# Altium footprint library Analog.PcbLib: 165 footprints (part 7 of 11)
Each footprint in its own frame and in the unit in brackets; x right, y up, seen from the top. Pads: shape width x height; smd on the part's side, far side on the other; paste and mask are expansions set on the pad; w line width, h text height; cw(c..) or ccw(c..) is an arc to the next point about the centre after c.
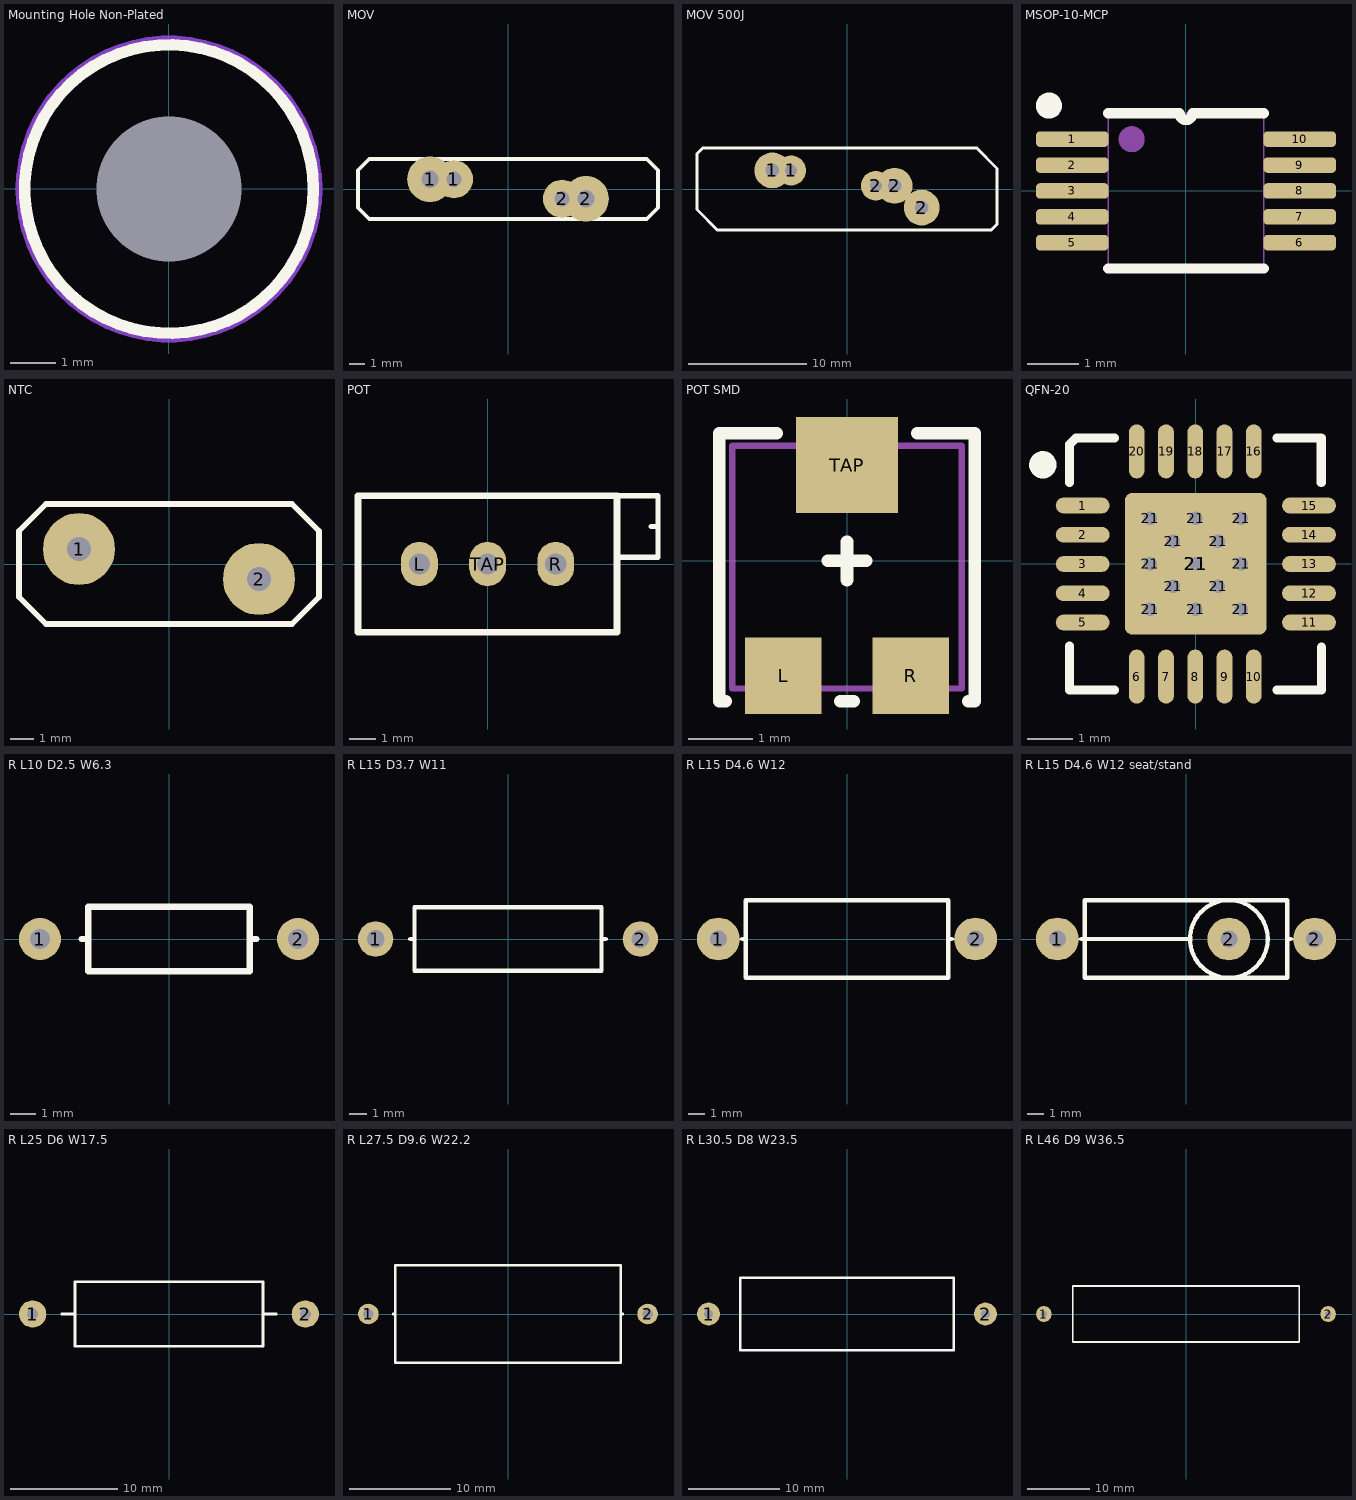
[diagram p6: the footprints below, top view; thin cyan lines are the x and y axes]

## Mounting Hole Non-Plated [mil]
pads (1):
  round 0 hole 126 unplated mask+120: 0(0,0)
Top Layer keep-out:
  circle w6: c0,0 r130
Bottom Layer keep-out:
  circle w6: c0,0 r130
Top Overlay:
  circle w10: c0,0 r125
Bottom Overlay:
  circle w10: c0,0 r125

## MOV [mil]
pads (4):
  round 120 hole 45: 1(-204.72,25.59) 2(204.72,-25.59)
  round 100 hole 40: 1(-141.73,25.59) 2(141.73,-25.59)
Top Overlay:
  lines w10: -393.7,-49.21 -393.7,49.21 -364.17,78.74 364.17,78.74 393.7,49.21 393.7,-49.21 364.17,-78.74 -364.17,-78.74 -393.7,-49.21

## MOV 500J [mil]
pads (5):
  round 120 hole 45: 1(-250,62.01) 2(159.45,10.83) 2(250,-62.01)
  round 100 hole 40: 1(-187.01,62.01) 2(96.46,10.83)
Top Overlay:
  lines w10: -501.97,-68.9 -501.97,118.11 -482.28,137.8 433.07,137.8 501.97,68.9 501.97,-118.11 482.28,-137.8 -433.07,-137.8 -501.97,-68.9

## MSOP-10-MCP [mm] "=VSSOP-10-TI"
pads (10):
  rrect50% 1.4x0.3 smd mask+0.05: 1(-2.2,1) 2(-2.2,0.5) 3(-2.2,0) 4(-2.2,-0.5) 5(-2.2,-1) 6(2.2,-1) 7(2.2,-0.5) 8(2.2,0) 9(2.2,0.5) 10(2.2,1)
Top Overlay:
  circle w0.254: c-2.65,1.65 r0.125
  lines w0.2: -1.5,-1.5 1.5,-1.5 ; -1.5,1.5 -0.125,1.5 ccw(c0,1.5) 0.125,1.5 1.5,1.5
Mechanical 13:
  circle w0.254: c-1.05,1 r0.125
  lines w0.025: -1.5,-1.5 1.5,-1.5 1.5,1.5 -1.5,1.5 -1.5,-1.5
  text ".Designator" at -0.325,1.3 h0.76

## NTC [mil]
pads (2):
  round 120 hole 40: 1(-150,25) 2(150,-25)
Top Overlay:
  lines w10: -250,-55 -205,-100 205,-100 250,-55 250,55 205,100 -205,100 -250,55 -250,-55

## POT [mil]
height 400
pads (3):
  oval 54x65 hole 31: L(-100,0) R(100,0) TAP(0,0)
Top Overlay:
  lines w8: 190,10 250,10 250,100 190,100 ; 240,55 250,55
  lines w10: -190,-100 190,-100 190,100 -190,100 -190,-100

## POT SMD [mm]
pads (3):
  rect 1.2x1.2 smd: L(-1,-1.8) R(1,-1.8)
  rect 1.6x1.5 smd: TAP(0,1.5)
Top Overlay:
  lines w0.2: -1.9,-2.2 -2,-2.2 -2,2 -1.1,2 ; -0.3,0 0.3,0 ; -0.1,-2.2 0.1,-2.2 ; 0,-0.3 0,0.3 ; 1.1,2 2,2 2,-2.2 1.9,-2.2
Mechanical 13:
  lines w0.1: -1.8,-2 -1.8,1.8 1.8,1.8 1.8,-2 -1.8,-2
  text ".Designator" at -1.675,-0.65 h1.02

## QFN-20 [mm]
pads (34):
  oval 1.2x0.35 smd: 1(-2.515,1.295) 2(-2.515,0.645) 3(-2.515,-0.005) 4(-2.515,-0.655) 5(-2.515,-1.305) 11(2.517,-1.305) 12(2.517,-0.655) 13(2.517,-0.005) 14(2.517,0.645) 15(2.517,1.295)
  oval 0.35x1.2 smd: 6(-1.311,-2.508) 7(-0.661,-2.508) 8(-0.011,-2.508) 9(0.639,-2.508) 10(1.289,-2.508) 16(1.289,2.499) 17(0.639,2.499) 18(-0.011,2.499) 19(-0.661,2.499) 20(-1.311,2.499)
  round 0.508 hole 0.3: 21(-1.016,-1.016) 21(-1.016,0) 21(-1.016,1.016) 21(-0.5,-0.5) 21(-0.5,0.5) 21(0,-1.016) 21(0,1.016) 21(0.5,-0.5) 21(0.5,0.5) 21(1.016,-1.016) 21(1.016,0) 21(1.016,1.016)
  rrect10% 3.15x3.15 smd: 21(0,0)
  rrect10% 3.15x3.15 hole 0.3: 21(0,0)
Top Overlay:
  circle w0.305: c-3.4,2.2 r0.152
  lines w0.203: -2.811,-1.829 -2.811,-2.805 -1.803,-2.805 ; -2.811,1.803 -2.811,2.65 -2.666,2.795 -1.803,2.795 ; 1.803,-2.805 2.794,-2.805 2.794,-1.854 ; 1.803,2.795 2.789,2.795 2.789,1.803

## R L10 D2.5 W6.3 [mil]
pads (2):
  round 65 hole 31: 1(-200,0) 2(200,0)
Top Overlay:
  lines w10: -135,0 -125,0 ; 125,0 135,0 ; -125,-50 125,-50 125,50 -125,50 -125,-50

## R L15 D3.7 W11 [mil]
height 145.67
pads (2):
  round 80 hole 40: 1(-300,0) 2(300,0)
Top Overlay:
  lines w10: -222,0 -212,0 ; 212,0 222,0 ; -212,-72 212,-72 212,72 -212,72 -212,-72

## R L15 D4.6 W12 [mil]
height 181.1
pads (2):
  round 100 hole 40: 1(-300,0) 2(300,0)
Top Overlay:
  lines w10: -244.09,0 -236.22,0 ; 236.22,0 244.09,0 ; -236.22,-90.55 -236.22,90.55 236.22,90.55 236.22,-90.55 -236.22,-90.55

## R L15 D4.6 W12 seat/stand [mil]
height 181.1
pads (3):
  round 100 hole 40: 1(-300,0) 2(100,0) 2(300,0)
Top Overlay:
  circle w10: c100,0 r90.55
  lines w10: -244.09,0 -236.22,0 10,0 ; 236.22,0 244.09,0 ; -236.22,-90.55 236.22,-90.55 236.22,90.55 -236.22,90.55 -236.22,-90.55

## R L25 D6 W17.5 [mil]
height 181.1
pads (2):
  round 100 hole 40: 1(-500,0) 2(500,0)
Top Overlay:
  lines w10: -393.7,0 -344.49,0 ; 344.49,0 393.7,0 ; -344.49,-118.11 344.49,-118.11 344.49,118.11 -344.49,118.11 -344.49,-118.11

## R L27.5 D9.6 W22.2 [mil]
height 344
pads (2):
  round 80 hole 40: 1(-541.34,0) 2(541.34,0)
Top Overlay:
  lines w10: -444.88,0 -437.01,0 ; 437.01,0 444.88,0 ; -437.01,-188.98 437.01,-188.98 437.01,188.98 -437.01,188.98 -437.01,-188.98

## R L30.5 D8 W23.5 [mil]
height 344
pads (2):
  round 100 hole 40: 1(-600,0) 2(600,0)
Top Overlay:
  lines w10: -462.6,-157.48 462.6,-157.48 462.6,157.48 -462.6,157.48 -462.6,-157.48

## R L46 D9 W36.5 [mil]
height 344
pads (2):
  round 100 hole 40: 1(-900,0) 2(900,0)
Top Overlay:
  lines w10: -718.5,-177.17 -718.5,177.17 718.5,177.17 718.5,-177.17 -718.5,-177.17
